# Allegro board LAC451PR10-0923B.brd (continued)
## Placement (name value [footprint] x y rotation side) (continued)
RA21  100K_0402_5%  [R_0402]  300.58 73.69 180 top
RA24  4.7K_0402_5%  [R_0402]  290.5 62.07 180 top
RA25  4.7K_0402_5%  [R_0402]  291.36 62.07 0 top
RA26  100K_0402_5%  [R_0402]  275.1 53.5 0 top
RA27  200K_0402_5%  [R_0402]  279.83 55.29 180 top
RA28  100K_0402_5%  [R_0402]  275.1 52.61 0 top
RA29  100K_0402_5%  [R_0402]  280.98 53.31 180 top
RA30  22_0402_5%  [R_0402]  286.74 63.97 90 top
RA31  22_0402_5%  [R_0402]  288.43 63.04 180 top
RA32  33_0402_5%  [R_0402]  287.63 63.97 90 top
RA35  0_0402_5%  [R0402_0OHM]  300.5 63.53 0 top
RA36  0_0402_5%  [R0402_0OHM]  292.2 40.37 270 top
RA37  0_0402_5%  [R0402_0OHM]  283.96 57.1 90 top
RA38  100K_0402_5%  [R_0402]  280.07 54.2 0 top
RA39  0_0805_5%  [R0805_0OHM]  279.12 73.86 90 top
RA44  100K_0402_5%  [R_0402]  294.66 62.01 0 top
RA45  0_0402_5%  [R0402_0OHM]  281.99 52.36 180 top
RC1  100K_0402_5%  [R_0402]  167.89 95.61 0 top
RC2  24.9_0402_1%  [R_0402]  144.78 100.78 180 top
RC3  100_0402_1%  [R_0402]  164.82 112.1 90 top
RC4  200_0402_1%  [R_0402]  175.24 85.63 180 top
RC5  121_0402_1%  [R_0402]  162.69 75.11 270 top
RC6  80.6_0402_1%  [R_0402]  163.58 75.11 270 top
RC7  100_0402_1%  [R_0402]  165.95 73.33 270 top
RC10  1K_0402_1%  [R_0402]  185.27 87.58 180 bottom
RC11  1K_0402_1%  [R_0402]  182.31 72.39 90 top
RC12  1K_0402_5%  [R_0402]  177.01 98.6 90 top
RC13  10K_0402_5%  [R_0402]  174.9 68.54 180 top
RC14  1K_0402_5%  [R_0402]  177.9 98.6 90 top
RC15  1K_0402_5%  [R_0402]  178.84 94.95 180 top
RC16  22_0402_5%  [R_0402]  177.7 73.31 270 top
RC17  1K_0402_5%  [R_0402]  178.84 94.06 180 top
RC18  22_0402_5%  [R_0402]  176.81 73.31 270 top
RC19  499_0402_1%  [R_0402]  252.75 88.35 180 top
RC20  499_0402_1%  [R_0402]  252.75 89.37 180 top
RC21  10K_0402_1%  [R_0402]  172.82 74.13 90 top
RC22  22_0402_5%  [R_0402]  180.05 73.31 270 top
RC23  2.2K_0402_5%  [R_0402]  173.48 93.15 0 top
RC24  22_0402_5%  [R_0402]  179.16 73.31 270 top
RC25  10K_0402_5%  [R_0402]  176.96 92.59 270 top
RC26  10K_0402_5%  [R_0402]  171.93 75.04 270 top
RC27  8.2K_0402_5%  [R_0402]  173.71 75.04 270 top
RC28  33_0402_5%  [R_0402]  186.19 90.44 0 bottom
RC29  33_0402_5%  [R_0402]  186.28 100.95 270 bottom
RC30  1K_0402_5%  [R_0402]  196.71 87.71 90 bottom
RC31  1K_0402_5%  [R_0402]  202.14 87.71 90 bottom
RC32  0_0402_5%  [R_0402]  190.76 85.33 0 bottom
RC33  0_0402_5%  [R_0402]  192.52 85.33 0 bottom
RC34  0_0402_5%  [R_0402]  194.27 85.33 0 bottom
RC35  0_0402_5%  [R_0402]  196.54 85.73 0 bottom
RC36  0_0402_5%  [R_0402]  198.52 86.27 270 bottom
RC37  0_0402_5%  [R0402_0OHM]  198.22 98.26 90 bottom
RC38  0_0402_5%  [R_0402]  199.41 85.4 0 bottom
RC39  33_0402_5%  [R_0402]  197.58 95.72 90 bottom
RC40  0_0402_5%  [R_0402]  196.24 77.94 0 bottom
RC41  0_0402_5%  [R_0402]  203.71 86.83 180 bottom
RC42  0_0402_5%  [R_0402]  197.58 92.16 90 bottom
RC43  33_0402_5%  [R_0402]  195.82 87.71 90 bottom
RC44  113_0402_1%  [R_0402]  170.84 91.93 0 top
RC45  100_0402_1%  [R_0402]  171.68 99.91 90 top
RC46  1M_0402_1%  [R_0402]  153.59 110.22 180 bottom
RC47  10K_0402_5%  [R_0402]  191.28 78.65 0 top
RC48  1K_0402_5%  [R_0402]  167.75 73.37 270 top
RC50  10K_0402_5%  [R_0402]  191.28 75.98 0 top
RC51  10K_0402_5%  [R_0402]  191.28 76.87 0 top
RC52  2.7K_0402_1%  [R_0402]  160.7 95.88 0 top
RC54  10M_0402_5%  [R_0402]  180.44 88.54 90 top
RC56  20K_0402_5%  [R_0402]  169.53 73.34 270 top
RC57  20K_0402_5%  [R_0402]  170.41 73.34 270 top
RC59  10K_0402_5%  [R_0402]  180.87 78.39 0 bottom
RC60  0_0402_5%  [R_0402]  192.25 88.63 270 bottom
RC61  0_0402_5%  [R0402_0OHM]  194.92 88.63 270 bottom
RC62  0_0402_5%  [R0402_0OHM]  191.36 88.63 270 bottom
RC64  0_0402_5%  [R0402_0OHM]  194.03 88.63 270 bottom
RC65  100K_0402_5%  [R_0402]  187.03 87.21 180 bottom
RC67  1K_0402_5%  [R_0402]  176.3 68.72 270 top
RC68  10K_0402_5%  [R_0402]  179.89 66.88 270 top
RC69  1M_0402_5%  [R_0402]  181.43 73.3 270 top
RC71  1K_0402_5%  [R_0402]  130.86 108.85 270 bottom
RC72  8.2K_0402_5%  [R_0402]  180.98 71.05 270 top
RC73  10K_0402_5%  [R_0402]  174.6 75.04 270 top
RC74  10K_0402_5%  [R_0402]  190.93 79.79 180 top
RC75  10K_0402_5%  [R_0402]  166.88 72.45 90 top
RC76  43K_0402_1%  [R_0402]  259.56 81.76 90 top
RC77  1K_0402_5%  [R_0402]  122.58 99.6 0 bottom
RC78  60.4_0402_1%  [R_0402]  131.75 108.85 270 bottom
RC79  49.9_0402_1%  [R_0402]  138.02 109.33 270 bottom
RC80  1K_0402_5%  [R_0402]  136.15 109.05 0 bottom
RC81  51_0402_5%  [R_0402]  139.95 110.31 270 bottom
RC82  51_0402_5%  [R_0402]  142.59 109.32 270 bottom
RC83  1K_0402_5%  [R_0402]  129.08 107.93 90 bottom
RC84  499_0402_1%  [R_0402]  129.97 108.85 270 bottom
RC86  51_0402_5%  [R_0402]  140.85 108.8 270 bottom
RC87  1K_0402_5%  [R_0402]  138.97 108.42 90 bottom
RC88  49.9_0402_1%  [R_0402]  171.93 72.37 270 top
RC89  49.9_0402_1%  [R_0402]  172.82 72.37 270 top
RC90  49.9_0402_1%  [R_0402]  135.27 98.69 180 top
RC91  49.9_0402_1%  [R_0402]  135.27 97.8 180 top
RC92  33_0402_5%  [R_0402]  166.27 69.59 90 top
RC93  33_0402_5%  [R_0402]  164.49 69.59 90 top
RC94  33_0402_5%  [R_0402]  161.11 68.17 90 top
RC95  33_0402_5%  [R_0402]  162.88 68.17 90 top
RC96  200_0402_1%  [R_0402]  169.97 92.72 180 top
RC109  1K_0402_5%  [R_0402]  127.4 99.6 0 bottom
RC110  10K_0402_1%  [R_0402]  126.03 100.62 180 bottom
RC112  10K_0402_1%  [R_0402]  127.4 100.62 0 bottom
RC113  10K_0402_1%  [R_0402]  127.28 107.95 0 bottom
RC114  49.9_0402_1%  [R_0402]  139.85 100.09 180 top
RC115  1.5K_0402_5%  [R_0402]  172.12 111.69 90 top
RC119  0_0402_5%  [R_0402]  108.91 69.93 90 top
RC120  100K_0402_5%  [R_0402]  132.64 107.93 90 bottom
RC121  1K_0402_5%  [R_0402]  117.46 128.34 0 bottom
RC122  0_0402_5%  [R_0402]  116.58 128.22 90 bottom
RC123  1K_0402_5%  [R_0402]  112.44 123.48 180 bottom
RC124  1K_0402_5%  [R_0402]  109.24 123.48 0 bottom
RC126  1K_0402_5%  [R_0402]  121.18 126.65 0 top
RC128  0_0402_5%  [R_0402]  128.69 126.93 180 top
RC129  0_0402_5%  [R_0402]  129.58 128.09 90 top
RC130  51_0402_5%  [R_0402]  145.06 121.7 0 bottom
RC131  51_0402_5%  [R_0402]  137.94 121.7 0 bottom
RC132  150_0402_5%  [R_0402]  125.32 130.41 270 top
RC133  1.5K_0402_5%  [R_0402]  130.63 126.93 180 top
RC134  51_0402_5%  [R_0402]  137.94 120.81 0 bottom
RC135  51_0402_5%  [R_0402]  137.92 119.05 0 bottom
RC136  51_0402_5%  [R_0402]  145.97 119.8 180 bottom
RC137  1K_0402_5%  [R_0402]  136.15 119.48 270 top
RC138  51_0402_5%  [R_0402]  111.59 125.99 0 bottom
RC139  51_0402_5%  [R_0402]  131.32 117.75 0 bottom
RC140  100_0402_1%  [R_0402]  156.82 106.42 270 bottom
RC141  100_0402_1%  [R_0402]  155.94 105.51 90 bottom
RC143  0_0603_5%  [R0603_0OHM]  160.35 111.5 180 top
RC152  56_0402_1%  [R_0402]  134.41 108.85 270 bottom
RC153  220_0402_5%  [R_0402]  135.3 107.93 90 bottom
RC157  100_0402_1%  [R_0402]  133.53 108.85 270 bottom
RC161  100_0402_1%  [R_0402]  130.71 98.21 0 top
RC163  100_0402_1%  [R_0402]  132.55 98.21 0 top
RC165  100_0402_1%  [R_0402]  158.44 87.33 0 top
RC166  100_0402_1%  [R_0402]  155.06 105.51 90 bottom
RC167  100_0402_1%  [R_0402]  160.24 87.19 90 top
RC168  100_0402_1%  [R_0402]  154.18 106.42 270 bottom
RC169  0_0603_5%  [R0603_0OHM]  172.44 111.63 270 bottom
RC170  0_0402_5%  [R0402_0OHM]  164.78 114.6 180 top
RC171  0_0402_5%  [R0402_0OHM]  166.9 111.86 270 bottom
RC173  0_0402_5%  [R0402_0OHM]  164.12 111.86 270 bottom
RC175  2.2K_0402_5%  [R_0402]  174.74 94.22 180 top
RC176  2.2K_0402_5%  [R_0402]  173.29 96.88 0 top
RC177  2.2K_0402_5%  [R_0402]  173.29 95.99 0 top
RC178  2.2K_0402_5%  [R_0402]  174.74 95.1 180 top
RC179  100K_0402_5%  [R_0402]  143.75 111.15 270 bottom
RC180  100K_0402_5%  [R_0402]  144.64 111.15 270 bottom
RC181  100K_0402_5%  [R_0402]  148.18 111.15 270 bottom
RC182  100K_0402_5%  [R_0402]  147.3 111.15 270 bottom
RC183  8.2K_0402_5%  [R_0402]  184.66 73.3 270 top
RC184  8.2K_0402_5%  [R_0402]  171.66 86.51 270 top
RC186  4.7K_0402_5%  [R_0402]  183.26 72.39 90 top
RC187  4.7K_0402_5%  [R_0402]  162.01 69.96 180 top
RC189  10K_0402_5%  [R_0402]  191.28 77.76 0 top
RC190  10K_0402_5%  [R_0402]  190.42 78.65 180 top
RC194  0_0805_5%  [R_0805]  192.82 93.47 270 top
RC211  0_0402_5%  [R0402_0OHM]  187.93 73.17 90 top
RC212  0_0402_5%  [R_0402]  189.2 73.17 90 top
RC214  0_0402_5%  [R0402_0OHM]  180.98 65.39 90 top
RC215  0_0402_5%  [R_0402]  175.35 66.96 270 top
RC216  0_0603_1%  [R0603_0OHM]  113.76 125.38 180 top
RC217  0_0402_5%  [R_0402]  124.43 130.41 270 top
RC218  150_0402_5%  [R_0402]  122.67 129.89 90 top
RC219  10K_0402_5%  [R_0402]  123.54 129.5 90 top
RC220  100K_0402_1%  [R_0402]  176.3 66.96 270 top
RC221  0_0402_5%  [R0402_0OHM]  186.18 120.35 270 bottom
RC222  1K_0402_5%  [R_0402]  184.08 127.08 0 bottom
RC223  1K_0402_5%  [R_0402]  161.99 68.17 90 top
RC224  1K_0402_5%  [R_0402]  178.53 109.2 270 bottom
RC225  8.2K_0402_5%  [R_0402]  176.88 114.02 0 bottom
RC227  8.2K_0402_5%  [R_0402]  178.67 114.91 270 bottom
RC228  0_0402_5%  [R0402_0OHM]  145.06 120.81 0 bottom
RC229  0_0402_5%  [R0402_0OHM]  138.83 119.93 180 bottom
RC230  0_0402_5%  [R0402_0OHM]  139.41 117.55 180 bottom
RC231  0_0402_5%  [R0402_0OHM]  153.88 87.56 0 top
RC234  0_0402_5%  [R_0402]  182.76 90.69 180 bottom
RC235  0_0402_5%  [R0402_0OHM]  181.51 92.44 270 bottom
RC237  10K_0402_5%  [R_0402]  175.58 99.31 270 top
RC238  0_0603_5%  [R_0603]  161.07 112.18 270 bottom
RC239  0_0402_5%  [R_0402]  111.53 124.62 0 bottom
RC240  0_0402_5%  [R_0402]  110.12 125.47 180 bottom
RC241  1.5K_0402_5%  [R_0402]  112.44 122.34 180 bottom
RC242  100K_0402_5%  [R_0402]  173.3 97.76 90 top
RC243  10K_0402_5%  [R_0402]  185.39 68.66 90 top
RC244  0_0402_5%  [R0402_0OHM]  193.14 88.63 270 bottom
RC245  10K_0402_5%  [R_0402]  190.42 76.87 180 top
RC267  10K_0402_5%  [R_0402]  178.36 95.92 180 bottom
RC268  10K_0402_5%  [R_0402]  177.44 95.03 0 bottom
RC270  10K_0402_5%  [R_0402]  175.47 74.13 90 top
RC272  10K_0402_5%  [R_0402]  179.55 78.47 180 bottom
RC276  0_0402_5%  [R_0402]  203.71 85.97 270 bottom
RC278  10K_0402_5%  [R_0402]  179.73 98.21 0 bottom
RC279  10K_0402_5%  [R_0402]  190.42 77.76 180 top
RC281  10K_0402_5%  [R_0402]  179.73 95.92 0 bottom
RC282  100K_0402_5%  [R_0402]  173.47 85.63 180 top
RC283  10K_0402_5%  [R_0402]  191.89 87.92 0 top
RC287  100K_0402_5%  [R_0402]  192.2 75.09 180 top
RC288  10K_0402_5%  [R_0402]  179.79 77.3 180 bottom
RC289  0_0402_5%  [R0402_0OHM]  203.71 87.68 90 bottom
RC290  0_0402_5%  [R0402_0OHM]  179.42 108.29 90 bottom
RC291  10K_0402_5%  [R_0402]  177.65 109.2 270 bottom
RC292  10K_0402_5%  [R_0402]  179.17 92.53 180 bottom
RC295  0_0402_5%  [R0402_0OHM]  154.45 110.22 0 bottom
RC296  0_0402_5%  [R0402_0OHM]  181.32 88.55 0 top
RC297  0_0402_5%  [R_0402]  145.54 110.23 90 bottom
RC298  0_0402_5%  [R_0402]  146.42 110.23 90 bottom
RC299  0_0603_5%  [R0603_0OHM]  166.34 117.32 270 bottom
RC300  0_0402_5%  [R0402_0OHM]  169.59 113.24 270 top
RC301  0_0402_5%  [R0402_0OHM]  191.55 94.92 180 top
RC302  0_0402_5%  [R0402_0OHM]  171.04 112.37 270 top
RC303  0_0402_5%  [R0402_0OHM]  166.15 113.48 270 top
RC304  0_0402_5%  [R0402_0OHM]  173.01 91.02 180 top
RC305  0_0402_5%  [R0402_0OHM]  167.79 89.76 180 top
RC306  0_0402_5%  [R0402_0OHM]  177.91 88.9 180 top
RC307  0_0402_5%  [R0402_0OHM]  177.91 90.09 180 top
RC308  0_0402_5%  [R0402_0OHM]  174.25 92.18 180 top
RC309  0_0603_5%  [R0603_0OHM]  176.88 112.75 270 top
RC310  0_0603_5%  [R0603_0OHM]  174.98 112.75 270 top
RC311  10K_0402_5%  [R_0402]  164.95 74.25 90 top
RC312  100K_0402_5%  [R_0402]  170.72 98.34 270 top
RC313  0_0402_5%  [R_0402]  170.65 93.79 180 top
RC316  1K_0402_5%  [R_0402]  201.24 88.63 270 bottom
RC317  150K_0402_5%  [R_0402]  183.28 88.18 270 bottom
RC318  2.2K_0402_5%  [R_0402]  156.93 122.27 0 bottom
RC319  2.2K_0402_5%  [R_0402]  156.93 123.16 0 bottom
RC320  0_0402_5%  [R_0402]  159.1 120.7 270 bottom
RC323  10K_0402_5%  [R_0402]  181.86 70.13 90 top
RC324  2.7K_0402_1%  [R_0402]  160.84 94.41 270 top
RC325  0_0402_5%  [R0402_0OHM]  190.22 86.45 180 bottom
RC326  150K_0402_5%  [R_0402]  179.16 89.61 180 bottom
RC327  0_0402_5%  [R0402_0OHM]  180.92 89.61 180 bottom
RC328  0_0402_5%  [R0402_0OHM]  136.62 110.42 180 bottom
RC330  49.9K_0402_1%  [R_0402]  179.52 91.37 270 bottom
RC331  49.9K_0402_1%  [R_0402]  178.62 91.37 270 bottom
RC337  0_0402_5%  [R0402_0OHM]  173.87 89.04 0 top
RC338  1K_0402_5%  [R_0402]  173.02 90.13 0 top
RC339  0_0402_5%  [R_0402]  181.51 87.83 270 bottom
RC340  0_0402_5%  [R_0402]  182.38 87.83 270 bottom
RC341  10K_0402_5%  [R_0402]  190.52 105.37 270 top
RC342  10K_0402_5%  [R_0402]  190.03 106.64 0 top
RC344  10K_0402_5%  [R_0402]  179.89 67.75 90 top
RC345  100K_0402_5%  [R_0402]  180.62 77.3 0 bottom
RC346  10K_0402_5%  [R_0402]  179.74 114.6 270 top
RC347  499_0402_1%  [R_0402]  254.15 88.35 0 top
RC348  499_0402_1%  [R_0402]  254.15 89.37 0 top
RC349  100_0402_1%  [R_0402]  187.89 77.94 0 bottom
RD2  470_0402_1%  [R_0402]  107.74 41.21 90 top
RD4  1K_0402_5%  [R_0402]  197.23 39.61 180 top
RD18  1K_0402_1%  [R_0402]  126.24 42.16 270 top
RD19  2_0402_1%  [R_0402]  128.8 42.16 270 top
RD20  1K_0402_1%  [R_0402]  127.85 42.16 270 top
RD21  24.9_0402_1%  [R_0402]  130.67 42.16 0 top
RD22  1K_0402_1%  [R_0402]  206.69 42.02 270 top
RD24  1K_0402_1%  [R_0402]  208.82 42.02 0 top
RD25  24.9_0402_1%  [R_0402]  210.64 41.11 0 top
RD29  0_0402_5%  [R0402_0OHM]  107.74 43.9 270 top
RD30  100K_0402_5%  [R_0402]  81.63 40.6 90 top
RD60  0_0603_5%  [R0603_0OHM]  228.95 52.27 270 top
RD61  1K_0402_5%  [R_0402]  116.76 42.41 270 top
RD62  0_0402_5%  [R_0402]  156.52 46.12 180 top
RD63  0_0402_5%  [R_0402]  156.52 47.1 180 top
RD64  0_0402_5%  [R_0402]  133.63 39.47 180 top
RD65  0_0603_5%  [R0603_0OHM]  147.8 49.64 90 top
RD66  0_0402_5%  [R0402_0OHM]  152.85 46.12 0 top
RD67  0_0402_5%  [R0402_0OHM]  152.85 47.1 0 top
RD68  0_0402_5%  [R0402_0OHM]  126.87 39.48 0 top
RD69  0_0402_5%  [R_0402]  230.48 41.77 180 top
RD70  0_0402_5%  [R0402_0OHM]  230.48 40.88 180 top
RD71  0_0402_5%  [R_0402]  213.03 39.53 180 top
RD72  0_0402_5%  [R0402_0OHM]  228.74 41.77 180 top
RD73  0_0402_5%  [R_0402]  228.74 40.88 180 top
RD74  0_0402_5%  [R0402_0OHM]  207.66 39.52 0 top
RD75  2_0402_1%  [R_0402]  207.93 42.02 270 top
RE5  100K_0402_5%  [R_0402]  226.16 75.93 270 top
RE8  100K_0402_5%  [R_0402]  241.26 62.7 180 top
RE9  100K_0402_5%  [R_0402]  230.17 58.5 90 top
RE10  100K_0402_5%  [R_0402]  231.06 58.5 90 top
RE11  100K_0402_5%  [R_0402]  241.6 69.63 180 top
RE12  100K_0402_5%  [R_0402]  224.18 71.41 0 top
RE17  100K_0402_5%  [R_0402]  227.94 75.93 270 top
RE20  100K_0402_5%  [R_0402]  224.18 70.52 0 top
RE21  10K_0402_5%  [R_0402]  225.73 58.5 90 top
RE24  10K_0402_5%  [R_0402]  239.75 74.76 90 top
RE25  100K_0402_5%  [R_0402]  227.51 58.5 90 top
RE26  10_0402_5%  [R_0402]  226.62 58.5 90 top
RE27  33_0402_5%  [R_0402]  229.72 75.01 90 top
RE31  100K_0402_5%  [R_0402]  242.42 79.36 270 top
RE32  0_0402_5%  [R0402_0OHM]  242.94 82.56 270 top
RE33  10K_0402_5%  [R_0402]  244.19 78.44 90 top
RE35  10K_0402_5%  [R_0402]  264.34 73.69 180 top
RE36  100K_0402_5%  [R_0402]  227.05 75.93 270 top
RE38  10K_0402_5%  [R_0402]  224.18 69.63 0 top
RE42  10K_0402_5%  [R_0402]  244.19 75.9 90 top
RE48  10K_0402_5%  [R_0402]  254.73 58.38 90 top
RE51  10K_0402_5%  [R_0402]  253.85 56.76 180 top
RE55  100K_0402_5%  [R_0402]  255.62 58.38 90 top
RE56  10K_0402_5%  [R_0402]  258.04 75.64 270 top
RE57  1K_0402_5%  [R_0402]  257.02 77.81 90 top
RE58  100K_0402_5%  [R_0402]  256.13 77.81 90 top
RE59  0_0402_5%  [R0402_0OHM]  260.58 75.01 90 top
RE60  43_0402_5%  [R_0402]  261.47 75.01 90 top
RE62  100K_0402_5%  [R_0402]  242.34 75.92 0 top
RE63  100K_0402_5%  [R_0402]  258.8 78.72 270 top
RE64  4.7K_0402_5%  [R_0402]  257.91 77.81 90 top
RE65  100_0402_1%  [R_0402]  260.58 77.81 90 top
RE66  10_0402_5%  [R_0402]  257.4 59.29 270 top
RE67  10K_0402_5%  [R_0402]  249.76 57.88 180 top
RE68  100K_0402_5%  [R_0402]  247.99 58.77 270 top
RE69  8.2K_0402_5%  [R_0402]  259.21 58.4 180 top
RE70  2.2K_0402_5%  [R_0402]  262.46 54.9 90 top
RE71  49.9_0402_1%  [R_0402]  274.06 18.17 270 top
RE72  10K_0402_5%  [R_0402]  280.63 10.28 180 top
RE73  10K_0402_5%  [R_0402]  280.63 8.5 180 top
RE74  10K_0402_5%  [R_0402]  280.63 7.62 180 top
RE75  100K_0402_5%  [R_0402]  280.63 9.39 180 top
RE77  1.58K_0402_1%  [R_0402]  250 60.16 270 top
RE78  1K_0402_5%  [R_0402]  255.75 56.09 90 top
RE79  1K_0402_5%  [R_0402]  245.39 67.73 0 top
RE81  10K_0402_5%  [R_0402]  242.01 82.56 270 top
RE82  10K_0402_5%  [R_0402]  241.12 82.56 270 top
RE84  100K_0402_5%  [R_0402]  233.73 59.42 270 top
RE85  100K_0402_5%  [R_0402]  232.84 59.42 270 top
RE86  10K_0402_5%  [R_0402]  265.96 54.77 0 top
RE88  10K_0402_5%  [R_0402]  264.82 69.3 270 top
RE90  0_0402_5%  [R_0402]  264.26 54.66 180 top
RE274  0_0402_5%  [R_0402]  267.82 55.65 90 top
RE275  0_0402_5%  [R0402_0OHM]  264.34 74.58 180 top
RE277  100K_0402_5%  [R_0402]  252.19 57.67 90 top
RE280  0_0402_5%  [R_0402]  251.47 55.8 180 top
RE288  100_0402_5%  [R_0402]  230.53 39.59 180 top
RE290  0_0402_5%  [R0402_0OHM]  247.44 75.85 180 top
RE292  0_0402_5%  [R_0402]  252.11 56.66 180 top
RE298  100K_0402_5%  [R_0402]  234.62 59.42 270 top
RE299  100K_0402_5%  [R_0402]  235.51 59.42 270 top
RE300  240K_0402_5%  [R_0402]  241.26 61.74 0 top
RE301  10K_0402_5%  [R_0402]  256.66 75.01 90 top
RE304  0_0402_5%  [R_0402]  250.8 81.67 0 top
RE305  0_0402_5%  [R0402_0OHM]  239.89 61.73 270 top
RE306  0_0402_5%  [R_0402]  239.89 59.01 90 top
RE308  0_0402_5%  [R_0402]  262.38 68.59 0 top
RE312  0_0402_5%  [R0402_0OHM]  253.48 82.79 270 top
RE313  10K_0402_5%  [R_0402]  254.42 81.56 0 top
RI13  10K_0402_5%  [R_0402]  274.15 101.63 270 top
RI14  22.1K_0402_1%  [R_0402]  277.43 105.11 180 top
RI15  0_0402_5%  [R0402_0OHM]  284.12 99.09 0 bottom
RI16  0_0402_5%  [R0402_0OHM]  284.12 99.98 0 bottom
RI17  0_0402_5%  [R0402_0OHM]  284.12 97.32 0 bottom
RI18  0_0402_5%  [R0402_0OHM]  284.12 98.21 0 bottom
RI19  0_0402_5%  [R0402_0OHM]  65.44 122.77 90 top
RI20  0_0402_5%  [R0402_0OHM]  64.55 122.77 90 top
RI21  0_0402_5%  [R0402_0OHM]  67.22 122.77 90 top
RI22  0_0402_5%  [R0402_0OHM]  66.33 122.77 90 top
RI23  0_0402_5%  [R0402_0OHM]  90.65 122.77 90 top
RI24  0_0402_5%  [R0402_0OHM]  89.76 122.77 90 top
RI25  0_0402_5%  [R0402_0OHM]  92.43 122.77 90 top
RI26  0_0402_5%  [R0402_0OHM]  91.54 122.77 90 top
RI27  0_0402_5%  [R0402_0OHM]  277.63 96.05 0 top
RI28  0_0402_5%  [R0402_0OHM]  277.63 95.16 0 top
RI29  0_0402_5%  [R0402_0OHM]  277.63 97.82 0 top
RI30  0_0402_5%  [R0402_0OHM]  277.63 96.94 0 top
RI31  0_0402_5%  [R0402_0OHM]  285.8 123.06 0 top
RL1  10K_0402_5%  [R_0402]  253.9 91.6 0 top
RL2  10K_0402_5%  [R_0402]  253.9 90.71 0 top
RL3  0_0402_5%  [R0402_0OHM]  269.29 91.86 180 top
RL4  4.7K_0402_5%  [R_0402]  264.45 88.76 270 top
RL5  10K_0402_5%  [R_0402]  267.12 87.84 90 top
RL6  4.7K_0402_5%  [R_0402]  265.34 87.84 90 top
RL7  0_0402_5%  [R0402_0OHM]  268.89 87.84 90 top
RL8  0_0603_5%  [R0603_0OHM]  267.01 90.65 180 top
RL9  10K_0402_5%  [R_0402]  268.01 88.76 270 top
RL11  1M_0402_5%  [R_0402]  265.02 96.73 90 top
RL12  1K_0402_5%  [R_0402]  254.81 92.49 180 top
RL13  3.01K_0402_1%  [R_0402]  263.88 98.51 90 top
RL14  150_0402_5%  [R_0402]  287.75 120.86 90 top
RL15  75_0402_1%  [R_0402]  269.59 123.55 270 top
RL16  75_0402_1%  [R_0402]  270.86 123.55 270 top
RL17  75_0402_1%  [R_0402]  277.21 123.55 270 top
RL18  75_0402_1%  [R_0402]  278.48 123.55 270 top
RL19  150_0402_5%  [R_0402]  283.08 115.52 90 top
RL20  150_0402_5%  [R_0402]  284.81 118 90 top
RL29  1M_0402_5%  [R_0402]  286.87 121.78 270 top
RL30  1M_0402_5%  [R_0402]  280.91 115.48 0 top
RL34  0_0402_5%  [R0402_0OHM]  267.13 95.86 180 top
RL70  10K_0402_5%  [R_0402]  266.24 87.84 90 top
RL71  2.2_0603_5%  [R_0603]  265.28 103.15 90 top
RL72  2.2_0603_5%  [R_0603]  263.88 103.15 90 top
RL73  2.2_0603_5%  [R_0603]  262.48 103.15 90 top
RL74  2.2_0603_5%  [R_0603]  261.08 103.15 90 top
RL75  2.2_0603_5%  [R_0603]  259.69 103.15 90 top
RL76  2.2_0603_5%  [R_0603]  258.29 103.15 90 top
RL77  2.2_0603_5%  [R_0603]  256.89 103.15 90 top
RL78  2.2_0603_5%  [R_0603]  255.5 103.15 90 top
RN25  10K_0402_5%  [R_0402]  24.86 59.8 270 top
RN26  10K_0402_5%  [R_0402]  22.18 57.31 0 top
RN27  10K_0402_5%  [R_0402]  23.78 49.96 90 top
RN28  10K_0402_5%  [R_0402]  22.18 56.42 0 top
RN30  4.99K_0402_1%  [R_0402]  23.1 54.64 180 top
RN31  4.99K_0402_1%  [R_0402]  37.01 54.26 180 top
RN37  10K_0402_5%  [R_0402]  15.83 38.32 0 top
RN38  10K_0402_5%  [R_0402]  23.94 59.56 180 top
RN39  10K_0402_5%  [R_0402]  23.05 58.2 180 top
RN40  10K_0402_5%  [R_0402]  24.67 50.87 270 top
RN41  10K_0402_5%  [R_0402]  23.1 55.53 180 top
RN42  10K_0402_5%  [R_0402]  30.57 56.8 0 top
RN43  10K_0402_5%  [R_0402]  30.57 55.79 0 top
RN44  10K_0402_5%  [R_0402]  31.15 49.96 90 top
RN45  10K_0402_5%  [R_0402]  32.47 56.8 0 top
RN46  10K_0402_5%  [R_0402]  32.47 55.79 0 top
RN47  10K_0402_5%  [R_0402]  32.04 50.87 270 top
RN49  10K_0402_5%  [R_0402]  22.18 53.76 0 top
RN50  10K_0402_5%  [R_0402]  30.57 54.77 0 top
RN51  10K_0402_5%  [R_0402]  30.26 49.96 90 top
RN52  10K_0402_5%  [R_0402]  23.1 52.87 180 top
RN53  10K_0402_5%  [R_0402]  32.47 54.77 0 top
RN54  10K_0402_5%  [R_0402]  29.37 50.87 270 top
RN55  10K_0402_5%  [R_0402]  38.96 59.04 270 top
RN56  10K_0402_5%  [R_0402]  36.09 56.93 0 top
RN57  10K_0402_5%  [R_0402]  37.87 50.96 0 top
RN58  10K_0402_5%  [R_0402]  36.09 56.04 0 top
RN59  10K_0402_5%  [R_0402]  38.07 58.12 90 top
RN60  10K_0402_5%  [R_0402]  37.01 57.82 180 top
RN61  10K_0402_5%  [R_0402]  38.77 50.02 270 top
RN62  10K_0402_5%  [R_0402]  37.01 55.15 180 top
RN63  10K_0402_5%  [R_0402]  44.54 56.42 0 top
RN64  10K_0402_5%  [R_0402]  44.54 55.41 0 top
RN65  10K_0402_5%  [R_0402]  44.54 53.37 0 top
RN66  10K_0402_5%  [R_0402]  46.31 56.42 0 top
RN67  10K_0402_5%  [R_0402]  46.31 55.41 0 top
RN68  10K_0402_5%  [R_0402]  46.31 53.37 0 top
RN69  10K_0402_5%  [R_0402]  36.09 53.37 0 top
RN70  10K_0402_5%  [R_0402]  44.54 54.39 0 top
RN71  10K_0402_5%  [R_0402]  44.42 50.12 90 top
RN72  10K_0402_5%  [R_0402]  37.01 52.49 180 top
RN73  10K_0402_5%  [R_0402]  46.31 54.39 0 top
RN74  10K_0402_5%  [R_0402]  43.53 51.04 270 top
RN77  0_0402_5%  [R0402_0OHM]  25.69 49.96 90 top
RN78  0_0402_5%  [R0402_0OHM]  26.58 49.96 90 top
RN81  0_0402_5%  [R0402_0OHM]  39.72 50.12 90 top
RN82  0_0402_5%  [R0402_0OHM]  40.61 50.12 90 top
RN99  0_0402_5%  [R0402_0OHM]  11.28 39.45 90 bottom
RPC1  33_0804_8P4R_5%  [RP_0804_8P4R]  183.17 96.23 0 bottom
RPC2  33_0804_8P4R_5%  [RP_0804_8P4R]  183.2 93.02 0 bottom
RPC3  10K_8P4R_5%  [RP_0804_8P4R]  175.6 114.39 90 bottom
RPC4  10K_8P4R_5%  [RP_0804_8P4R]  177.86 100.94 0 bottom
RPC5  10K_8P4R_5%  [RP_0804_8P4R]  174.99 108.57 270 bottom
RPE2  4.7K_8P4R_5%  [RP_0804_8P4R]  264.07 64.94 180 top
RPE3  2.2K_0804_8P4R_5%  [RP_0804_8P4R]  246.19 69.08 180 top
RPE5  100K_0804_8P4R_5%  [RP_0804_8P4R]  246.17 73.07 180 top
RPE6  2.2K_0804_8P4R_5%  [RP_0804_8P4R]  262.92 72.54 0 top
RPE7  10K_8P4R_5%  [RP_0804_8P4R]  275.17 16.71 90 top
RPE8  100K_0804_8P4R_5%  [RP_0804_8P4R]  236.08 75.15 90 top
RPE9  100K_0804_8P4R_5%  [RP_0804_8P4R]  224.7 72.82 180 top
RPE10  100K_0804_8P4R_5%  [RP_0804_8P4R]  262.91 63.43 0 top
RPE11  100K_0804_8P4R_5%  [RP_0804_8P4R]  241.08 73.3 0 top
RPV1  2.2K_0804_8P4R_5%  [RP_0804_8P4R]  223.3 122.45 0 top
RPV2  2.2K_0804_8P4R_5%  [RP_0804_8P4R]  211.62 109.34 270 bottom
RR1  10_0402_5%  [R_0402]  272.25 78.39 0 top
RR16  10K_0402_5%  [R_0402]  268.23 85.89 270 top
RR17  0_0402_5%  [R0402_0OHM]  272.25 80.17 0 top
RR18  0_0402_5%  [R0402_0OHM]  272.7 81.47 0 top
RR19  10K_0402_5%  [R_0402]  265.91 83.92 0 top
RR20  6.2K_0402_1%  [R_0402]  264.59 78.01 180 top
RR21  0_0402_5%  [R0402_0OHM]  271.24 76.18 270 top
RR22  0_0402_5%  [R0402_0OHM]  272.13 76.18 270 top
RR23  0_0402_5%  [R0402_0OHM]  272.25 79.28 0 top
RV1  4.7K_0402_5%  [R_0402]  96.87 110.77 145 top
RV2  4.7K_0402_5%  [R_0402]  94.9 109.57 325 top
RV3  100K_0402_5%  [R_0402]  83.03 111.29 270 top
RV4  270K_0402_5%  [R_0402]  87.73 112.48 90 top
RV5  47K_0402_5%  [R_0402]  86.84 114.26 90 top
RV6  10K_0402_5%  [R_0402]  106.28 115.23 325 top
RV8  10K_0402_5%  [R_0402]  251.69 131.28 90 bottom
RV10  470_0402_1%  [R_0402]  232.55 127.5 90 bottom
RV11  470_0402_1%  [R_0402]  233.44 127.5 90 bottom
RV12  470_0402_1%  [R_0402]  234.33 127.5 90 bottom
RV13  470_0402_1%  [R_0402]  235.21 127.5 90 bottom
RV14  470_0402_1%  [R_0402]  230.77 127.5 90 bottom
RV15  470_0402_1%  [R_0402]  231.66 127.5 90 bottom
RV16  470_0402_1%  [R_0402]  236.1 127.5 90 bottom
RV17  470_0402_1%  [R_0402]  236.99 127.5 90 bottom
RV18  2.2K_0402_5%  [R_0402]  239.49 128.1 90 bottom
RV19  10K_0402_5%  [R_0402]  241.4 128.51 270 top
RV20  20K_0402_5%  [R_0402]  247.42 130.08 0 bottom
RV21  2.2K_0402_5%  [R_0402]  238.61 128.1 90 bottom
RV22  1M_0402_5%  [R_0402]  250.67 131.28 90 bottom
RV50  4.99K_0402_1%  [R_0402]  253.08 124.95 270 top
RV51  4.7K_0402_5%  [R_0402]  250.08 113.34 270 top
RV52  4.7K_0402_5%  [R_0402]  253.97 124.95 270 top
RV53  4.7K_0402_5%  [R_0402]  251.31 110.19 90 top
RV54  4.7K_0402_5%  [R_0402]  253.05 114.97 0 top
RV55  4.7K_0402_5%  [R_0402]  246.14 110.21 90 top
RV56  4.7K_0402_5%  [R_0402]  247.09 110.21 90 top
RV57  4.7K_0402_5%  [R_0402]  248.11 110.21 90 top
RV58  4.7K_0402_5%  [R_0402]  249.12 110.21 90 top
RV60  4.7K_0402_5%  [R_0402]  250.08 110.21 90 top
RV61  4.7K_0402_5%  [R_0402]  254.78 114.97 0 top
RV62  4.7K_0402_5%  [R_0402]  246.14 113.34 270 top
RV63  4.7K_0402_5%  [R_0402]  248.11 113.34 270 top
RV64  4.7K_0402_5%  [R_0402]  247.09 113.34 270 top
RV65  4.7K_0402_5%  [R_0402]  249.12 113.34 270 top
RV67  1M_0402_5%  [R_0402]  240.6 120.7 0 top
RV68  1M_0402_5%  [R_0402]  243.91 123.59 270 top
RV69  100K_0402_5%  [R_0402]  247.98 127.06 270 top
RV70  100K_0402_5%  [R_0402]  248.87 127.06 270 top
RV73  1M_0402_5%  [R_0402]  222.91 111.41 0 top
RV74  1M_0402_5%  [R_0402]  210.92 121.5 90 top
RV75  1M_0402_5%  [R_0402]  217.89 123.34 180 top
RV76  150_0402_1%  [R_0402]  226.11 113.45 180 top
RV77  150_0402_1%  [R_0402]  222.91 114.72 0 top
RV78  150_0402_1%  [R_0402]  226.11 114.72 180 top
RV79  100K_0402_5%  [R_0402]  209.84 109.01 270 top
RV80  1M_0402_5%  [R_0402]  221.83 110.21 0 top
RV81  2.2K_0402_5%  [R_0402]  224.52 110.21 180 top
RV82  1M_0402_5%  [R_0402]  218.74 123.34 0 top
RV83  2.2K_0402_5%  [R_0402]  212.49 108.97 270 top
RV84  1M_0402_5%  [R_0402]  211.6 108.97 270 top
RV85  1M_0402_5%  [R_0402]  210.03 121.5 90 top
RV86  10K_0402_5%  [R_0402]  201.9 112.23 90 bottom
RV87  2.2K_0402_5%  [R_0402]  203.3 105.71 0 bottom
RV88  10K_0402_5%  [R_0402]  223.82 112.43 180 top
RV89  3.74K_0402_1%  [R_0402]  222.91 113.45 0 top
RV90  100K_0402_5%  [R_0402]  206.14 121.95 0 bottom
RV91  100K_0402_5%  [R_0402]  206.55 116.34 180 bottom
RV100  4.7K_0402_5%  [R_0402]  251.31 112.48 90 top
RV501  100K_0402_5%  [R_0402]  216.63 125.31 90 bottom
RV502  100K_0402_5%  [R_0402]  215.75 125.31 90 bottom
RV503  5.1M_0402_5%  [R_0402]  212.82 125.31 90 bottom
RV508  1M_0402_5%  [R_0402]  195.6 120.81 0 bottom
RV509  1M_0402_5%  [R_0402]  195.6 115.22 0 bottom
RV516  2.2K_0402_5%  [R_0402]  210.73 109.01 270 top
RV517  2.2K_0402_5%  [R_0402]  214.25 108.33 90 bottom
RV518  2.2K_0402_5%  [R_0402]  213.27 123.3 180 top
RV519  2.2K_0402_5%  [R_0402]  214.36 121.38 180 bottom
RV600  4.99K_0402_1%  [R_0402]  227.43 114.51 90 top
RV601  4.7K_0402_5%  [R_0402]  243 111.67 180 top
RV602  4.7K_0402_5%  [R_0402]  228.32 115.43 270 top
RV603  4.7K_0402_5%  [R_0402]  238.1 115.43 270 top
RV604  100K_0402_5%  [R_0402]  226.08 107.86 0 top
RV605  100K_0402_5%  [R_0402]  226.08 109.64 0 top
RV606  1M_0402_5%  [R_0402]  241.22 105.32 180 top
RV607  1M_0402_5%  [R_0402]  226.08 105.95 0 top
RV608  100K_0402_5%  [R_0402]  226.08 108.75 0 top
RV609  100K_0402_5%  [R_0402]  226.08 110.52 0 top
RV610  4.7K_0402_5%  [R_0402]  243 113.83 180 top
RV611  4.7K_0402_5%  [R_0402]  243 107.73 180 top
RV612  4.7K_0402_5%  [R_0402]  243 108.8 180 top
RV613  4.7K_0402_5%  [R_0402]  243 109.71 180 top
RV614  4.7K_0402_5%  [R_0402]  243 110.78 180 top
RV615  4.7K_0402_5%  [R_0402]  243 112.94 180 top
RV616  4.7K_0402_5%  [R_0402]  242.08 114.72 0 top
RV617  4.7K_0402_5%  [R_0402]  241.22 107.73 180 top
RV618  4.7K_0402_5%  [R_0402]  241.22 108.8 180 top
RV619  4.7K_0402_5%  [R_0402]  241.22 109.71 180 top
RV620  4.7K_0402_5%  [R_0402]  241.22 110.78 180 top
RV621  4.7K_0402_5%  [R_0402]  237.21 114.51 90 top
RV622  10K_0402_5%  [R_0402]  221.97 125.31 90 bottom
RV623  10K_0402_5%  [R_0402]  96.06 101.38 180 bottom
RV647  5.6_0402_5%  [R_0402]  232.39 127.84 90 top
RV648  200_0402_5%  [R_0402]  233.3 129.93 180 top
RV649  5.6_0402_5%  [R_0402]  233.28 127.84 90 top
RV650  5.6_0402_5%  [R_0402]  234.19 127.84 90 top
RV651  200_0402_5%  [R_0402]  235.09 129.93 180 top
RV652  5.6_0402_5%  [R_0402]  235.08 127.85 90 top
RV653  5.6_0402_5%  [R_0402]  230.6 127.84 90 top
RV654  200_0402_5%  [R_0402]  231.47 129.91 180 top
RV655  5.6_0402_5%  [R_0402]  231.49 127.84 90 top
RV656  5.6_0402_5%  [R_0402]  235.99 127.85 90 top
RV657  200_0402_5%  [R_0402]  236.9 129.93 180 top
RV658  5.6_0402_5%  [R_0402]  236.89 127.85 90 top
RV659  27.4K_0402_1%  [R_0402]  223.83 105.2 180 bottom
RV660  88.7K_0402_1%  [R_0402]  221.94 105.2 180 bottom
RV661  100K_0402_5%  [R_0402]  220.19 107.1 180 bottom
RV662  0_0402_5%  [R0402_0OHM]  213.56 105.81 180 bottom
RZ8  2.2K_0402_5%  [R_0402]  289.41 11.41 270 bottom
RZ9  2.2K_0402_5%  [R_0402]  290.29 11.41 270 bottom
RZ10  1M_0402_5%  [R_0402]  296.31 10.75 180 bottom
RZ18  4.7K_0402_5%  [R_0402]  284.99 11.31 180 bottom
RZ19  4.7K_0402_5%  [R_0402]  284.99 12.21 180 bottom
RZ20  4.7K_0402_5%  [R_0402]  286.97 13.12 180 bottom
RZ21  4.7K_0402_5%  [R_0402]  286.97 14.02 180 bottom
RZ22  0_0402_5%  [R0402_0OHM]  281.68 11.27 0 bottom
RZ23  0_0402_5%  [R0402_0OHM]  281.68 12.18 0 bottom
RZ24  10K_0402_5%  [R_0402]  280.9 19.39 180 top
RZ25  150_0402_5%  [R_0402]  285.39 16.67 0 top
RZ26  0_0402_5%  [R_0402]  284.76 13.08 180 bottom
RZ27  150_0402_5%  [R_0402]  279.19 22.77 180 top
RZ28  330_0402_5%  [R_0402]  285.39 17.69 0 top
RZ29  0_0402_5%  [R_0402]  284.76 13.98 180 bottom
RZ32  150_0402_5%  [R_0402]  279.19 21.37 180 top
RZ34  150_0402_5%  [R_0402]  283.36 21.37 0 top
RZ38  100K_0402_5%  [R_0402]  237.72 58.5 90 top
RZ40  100K_0402_5%  [R_0402]  286.73 112.81 0 top
RZ43  0_0402_5%  [R0402_0OHM]  272.25 90.64 0 top
RZ56  0_0402_5%  [R0402_0OHM]  255.75 52.94 270 top
RZ58  33_0402_5%  [R_0402]  212.82 65.24 90 top
RZ59  33_0402_5%  [R_0402]  209.57 69.63 0 top
RZ60  33_0402_5%  [R_0402]  209.62 75.42 270 top
RZ61  0_0402_5%  [R0402_0OHM]  209.57 71.79 0 top
RZ62  10K_0402_5%  [R_0402]  214.98 66.15 270 top
RZ63  33_0402_5%  [R_0402]  210.51 75.42 270 top
RZ64  0_0402_5%  [R0402_0OHM]  195.32 77.11 90 top
RZ65  0_0402_5%  [R_0402]  194.43 77.11 90 top
RZ69  10K_0402_5%  [R_0402]  212.32 74.51 90 top
RZ70  0_0402_5%  [R0402_0OHM]  245.13 42.67 0 bottom
RZ71  0_0402_5%  [R_0402]  245.13 41.78 0 bottom
RZ72  0_0603_5%  [R_0603]  214.46 76.78 0 top
RZ76  0_0402_5%  [R_0402]  271.29 98.59 0 top
RZ77  0_0402_5%  [R_0402]  271.29 99.48 0 top
RZ78  0_0402_5%  [R_0402]  257.3 52.93 270 top
RZ79  0_0402_5%  [R_0402]  258.19 52.93 270 top
RZ80  0_0402_5%  [R_0402]  259.08 52.93 270 top
RZ81  0_0402_5%  [R_0402]  258.89 54.56 0 top
RZ82  0_0402_5%  [R_0402]  171.35 118.53 0 bottom
RZ83  0_0402_5%  [R_0402]  171.35 117.57 0 bottom
RZ84  0_0402_5%  [R_0402]  286.94 10.73 180 bottom
RZ85  0_0402_5%  [R0402_0OHM]  283.58 10.42 0 bottom
RZ86  0_0402_5%  [R0402_0OHM]  291.58 11.55 270 bottom
RZ87  0_0402_5%  [R_0402]  296.76 7.13 0 top
RZ88  0_0402_5%  [R_0402]  219.77 74.02 270 top
RZ89  0_0402_5%  [R0402_0OHM]  220.69 74.02 270 top
RZ90  10K_0402_5%  [R_0402]  216.01 65.26 90 top
RZ110  10K_0402_5%  [R_0402]  217.08 74.1 180 top
RZ111  10K_0402_5%  [R_0402]  221.28 76.39 270 top
RZ112  0_0402_5%  [R0402_0OHM]  216.93 65.26 90 top
RZ113  100_0402_5%  [R_0402]  217.92 74.1 0 top
RZ114  0_0402_5%  [R_0402]  294.55 11.83 270 bottom
RZ115  0_0402_5%  [R_0402]  293.66 11.83 270 bottom
RZ116  10K_0402_5%  [R_0402]  282.62 13.08 180 bottom
RZ117  10K_0402_5%  [R_0402]  282.62 13.99 180 bottom
RZ118  0_0402_5%  [R0402_0OHM]  284.19 16.72 180 top
RZ120  0_0402_5%  [R_0402]  112.1 74.38 0 top
ST2  -  [CLIP_C5P5]  84.1 97.36 180 bottom
SW1  SS3-CMFTQR9_3P  [SW_SS3-CMFTQR9_3P]  190.3 126.5 180 bottom
SW3  SKRBAAE010_4P  [SW_SKRBAAE010_4P]  293 118.75 270 top
T1  PAD~D  [TPC12]  148.54 99.73 0 top
T2  PAD~D  [TPC12]  146.71 99.74 0 top
T3  PAD~D  [TPC12]  140.93 77.58 180 bottom
T4  PAD~D  [TPC12]  139.68 76.96 180 bottom
T5  PAD~D  [TPC12]  143.08 87 0 top
T6  PAD~D  [TPC12]  143.05 85.45 0 top
T9  PAD~D  [TPC12]  121.64 99.6 180 bottom
T10  PAD~D  [TPC12]  143.56 107.18 180 bottom
T11  PAD~D  [TPC12]  142.26 106.21 180 bottom
T12  PAD~D  [TPC12]  129.7 77.81 180 bottom
T13  PAD~D  [TPC12]  128.31 77.81 180 bottom
T14  PAD~D  [TPC12]  166.62 88.59 0 top
T15  PAD~D  [TPC12]  168.35 88.32 0 top
T16  PAD~D  [TPC12]  128.31 79.16 180 bottom
T17  PAD~D  [TPC12]  129.7 79.16 180 bottom
T50  PAD~D  [TPC12]  125.64 39.85 0 top
T51  PAD~D  [TPC12]  127.74 48.99 0 top
T54  PAD~D  [TPC12]  205.34 39.63 0 top
T55  PAD~D  [TPC12]  207.07 49.09 0 top
T88  PAD~D  [TPC12]  255.71 92.49 270 top
T89  PAD~D  [TPC12]  255.69 91.21 270 top
T97  PAD~D  [TPC12]  236.92 69.45 180 bottom
T98  PAD~D  [TPC12]  240.12 63.66 0 top
T99  PAD~D  [TPC12]  240.21 70.48 0 top
T108  PAD~D  [TPC12]  225.3 112.52 90 top
T113  PAD~D  [TPC12]  129.7 80.5 180 bottom
T114  PAD~D  [TPC12]  128.31 80.5 180 bottom
T115  PAD~D  [TPC12]  166.85 85.38 0 top
T120  PAD~D  [TPC12]  166.82 96.31 0 top
T121  PAD~D  [TPC12]  180.92 74.18 0 top
T122  PAD~D  [TPC12]  156.37 97.53 0 top
T123  PAD~D  [TPC12]  155.38 88.71 0 top
T126  PAD~D  [TPC12]  183.8 78.39 180 bottom
T127  PAD~D  [TPC12]  185.27 78.39 180 bottom
T128  PAD~D  [TPC12]  177.34 84.59 180 bottom
T129  PAD~D  [TPC12]  176.29 85.61 180 bottom
T130  PAD~D  [TPC12]  177.68 78.39 180 bottom
T131  PAD~D  [TPC12]  242.87 69.82 0 top
T132  PAD~D  [TPC12]  124.75 74.56 0 top
TL1  MHPC_NS692417  [MHPC_NS692417_24P]  280.98 113.74 180 bottom
UA1  -  [ALC3235-CG_MQFN48_6X6]  286.01 72.24 270 top
UC1  SKL-U_BGA1356  [SKL-U_BGA_1356P-T]  174.07 103.21 0 bottom
UC5  -  [W25Q128FVSIQ_SO8]  196.05 100.03 270 bottom
UC6  -  [W25Q64FVSSIQ_SO8]  195.93 94.12 270 bottom
UC7  TC7SH08FU_SSOP5~D  [TC7SH08FU_SSOP5]  190.14 88.74 270 bottom
UC8  -  [74CBTLV3126BQ_DHVQFN14_2P5X3]  141.76 118.32 90 bottom
UC12  -  [74AHC1G09GW_TSSOP5]  177.25 112.56 0 bottom
UC13  TC7SH08FU_SSOP5~D  [TC7SH08FU_SSOP5]  162.09 121.08 270 bottom
UC14  TC7SH08FU_SSOP5~D  [TC7SH08FU_SSOP5]  88.53 118.26 90 top
UD1  -  [74AUP1G07GW_TSSOP5]  84 42.39 180 top
UE1  ECE5048-LZY_DQFN132_11X11~D  [ECE5048-LZY_DQFN132_11X11]  238.62 63.23 90 top
UE2  -  [MEC5085-LZY_DQFN132_11X11]  248.92 70.79 270 top
UE3  TC7SH08FU_SSOP5~D  [TC7SH08FU_SSOP5]  252.31 82.75 90 top
UE4  -  [74AUP1G07GW_TSSOP5]  248.91 80.72 90 top
UE5  TC7SH08FU_SSOP5~D  [TC7SH08FU_SSOP5]  254.72 54.2 90 top
UI1  -  [SY6288D20AAC_SOT23-5]  75.48 125.95 270 top
UI2  -  [SY6288D20AAC_SOT23-5]  96.82 125.82 270 top
UI3  -  [PI5USB2544ZHEX_TQFN16_3X3]  275.92 102.64 0 top
UL1  WGI219LM-QREF- A0_QFN48_6X6~D  [WGI217LM-QPN9-A2_QFN48_6X6]  263.17 91.69 90 top
UL2  TC7SH08FU_SSOP5~D  [TC7SH08FU_SSOP5]  254.67 95.4 90 top
UL4  -  [PI3L720ZHEX_TQFN42_9X3P5]  257.47 107.02 0 top
UN4  -  [PS8558BTQFN24GTR2-A_TQFN24_4X4]  28.08 57.08 270 top
UN5  -  [PS8558BTQFN24GTR2-A_TQFN24_4X4]  42.12 56.69 270 top
UR2  -  [RTS5242-GR_QFN32_4X4]  266.27 81.95 0 top
UV2  -  [AP2330W-7_SC59-3]  245.39 127.8 90 bottom
UV7  -  [PS8338BQFN60GTR-A0_QFN60_5X9]  250.72 115.75 90 top
UV8  VMM3320BJGR_BGA168  [VMM3320BJGR_BGA_168P-NH]  213.36 112.54 90 top
UV9  W25X10CVSNIG_SO8  [W25X10BVSNIG_SO8]  203.3 112.6 0 bottom
UV11  PI3C3125LEX_TSSOP14~D  [PI3C3125LEX_TSSOP14]  198.24 121.02 90 bottom
UV12  PI3C3125LEX_TSSOP14~D  [PI3C3125LEX_TSSOP14]  198.24 115.43 90 bottom
UV24  -  [G524B1T11U_SOT23-5]  86.9 109.18 180 top
UV26  -  [PS8338BQFN60GTR-A0_QFN60_5X9]  237.58 112.25 180 top
UV27  -  [SY6288D20AAC_SOT23-5]  218.86 126.07 0 bottom
UV28  -  [TPS22961DNYR_WSON8]  224.8 119.94 0 bottom
UV29  EM5106VT_DFN10_3X3  [APL5930QBI-TRG_TDFN10_3X3]  219.71 104.84 270 bottom
UZ2  EM5209VF_SON14_2X3  [TPS22966DPUR_SON14_2X3]  286.87 109.32 90 top
UZ3  EM5209VF_SON14_2X3  [TPS22966DPUR_SON14_2X3]  248.65 46.21 90 top
UZ4  EM5209VF_SON14_2X3  [TPS22966DPUR_SON14_2X3]  86.59 119.6 270 bottom
UZ5  EM5209VF_SON14_2X3  [TPS22966DPUR_SON14_2X3]  275.43 70.07 270 top
UZ6  TC7SH08FU_SSOP5~D  [TC7SH08FU_SSOP5]  265.98 71.04 270 top
UZ8  -  [AOZ1336_DFN8_2X2]  198.04 79.27 0 top
UZ10  TC7SH08FU_SSOP5~D  [TC7SH08FU_SSOP5]  280.07 15.67 270 top
UZ12  NPCT650JA0YX_QFN32_5X5  [NPCT650JAAYX_QFN32_5X5]  218.29 68.51 180 top
UZ19  -  [TPS22961DNYR_WSON8]  158.89 118.48 0 bottom
UZ20  -  [TPS22961DNYR_WSON8]  168.1 118.54 0 bottom
UZ21  -  [TPS22961DNYR_WSON8]  115.78 128.14 270 top
UZ22  -  [AOZ1336_DFN8_2X2]  194.67 79.83 0 top
UZ26  -  [TPS22961DNYR_WSON8]  112.97 71.17 90 top
YC1  24MHZ_12PF_X3G024000DC1H  [Y_X3G024000DC1H_4P]  155.11 112.35 180 bottom
YC2  32.768KHZ_12.5PF_9H03200042  [Y_9H03200042_2P]  179.51 90.99 0 top
YE1  32.768KHZ_12.5PF_Q13FC135000040  [Y_Q13FC135000040_2P]  249.25 78.52 180 top
YL1  25MHZ_18PF_7V25000034  [Y_7V25000034_4P]  266.66 99.43 270 top
YV2  27MHZ_12PF_X1E000021042600  [Y_X1E000021042600_4P]  222.14 106.42 0 top

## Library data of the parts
C33 CC210 CC219-CC221 CC225 CC226 CC271-CC274 CL28 PC5 PC7 PC104-PC110 PC117 PC118 PC120-PC124 PC201 PC202 PC305 PC306 PC308-PC311 PC508 PC511 PC608 PC612 PC656-PC658 PC672 PC673 PC801 PC803-PC807 PC811 PC812 PC814 PC818-PC820 PC822 PC826 PC827 PC835 PC902 PC1501 PC1503 = C_0805
C42 C43 C263 C294-C316 C319 CA1-CA6 CA12 CA13 CA19 CA22-CA24 CA27 CA28 CA33 CA35 CA41 CA54 CC3-CC8 CC21-CC27 CC32 CC33 CC174-CC179 CC181 CC182 CC185 CC186 CC194 CC195 CC199 CC202-CC209 CC211-CC213 CC215-CC218 CC222 CC224 CC248-CC257 CC264-CC266 CC269 CC288 CC297 CC300-CC308 CC310-CC314 CD2-CD4 CD6-CD11 CD24-CD27 CD31 CD35-CD44 CD54 CD57-CD60 CD63 CD70 CD71 CD74 CD75 CD78-CD85 CD102-CD109 CE8-CE10 CE12 CE14 CE15 CE24 CE26-CE30 CE34-CE40 CE44-CE47 CE52 CI4 CI5 CI13 CI16 CI27-CI31 CL1 CL2 CL5 CL6 CL13 CL14 CL18 CN20-CN26 CN30-CN36 CR23-CR27 CR35 CR37 CR42 CR43 CV1-CV6 CV10 CV11 CV13 CV14 CV17 CV18 CV21 CV22 CV28 CV29 CV60-CV62 CV71-CV80 CV85 CV86 CV89 CV92 CV93 CV96-CV99 CV102-CV111 CV113 CV115 CV119 CV120 CV122 CV123 CV145-CV150 CV152 CV153 CV156 CV157 CV374 CV501-CV509 CV603-CV613 CV616 CV619 CZ13 CZ14 CZ16 CZ20-CZ23 CZ30 CZ31 CZ37 CZ38 CZ41 CZ42 CZ45 CZ46 CZ51-CZ53 CZ55 CZ58 CZ59 CZ65-CZ69 CZ77 CZ84 CZ87 CZ90 CZ91 CZ95 CZ113 CZ115 PC3 PC4 PC100 PC101 PC103 PC113 PC115 PC116 PC127 PC128 PC203 PC204 PC210 PC212-PC214 PC301 PC303 PC307 PC401 PC402 PC408-PC411 PC417-PC420 PC503 PC505-PC507 PC509 PC510 PC601 PC602 PC605 PC613 PC614 PC616-PC621 PC624-PC633 PC636 PC637 PC639-PC647 PC649-PC654 PC659-PC661 PC677 PC679 PC680 PC685 PC686 PC688 PC809 PC810 PC815-PC817 PC823 PC824 PC829-PC831 PC833 PC834 PC901 PC903-PC905 PC1500 PC1502 PC1504 = C_0402
C317 C318 CA9 CA10 CA16 CA18 CA25 CA26 CA29 CA31 CA43 CA44 CA46 CA48 CA49 CA51-CA53 CC279 CC280 CC282-CC287 CC294-CC296 CD12-CD19 CD28 CD29 CD45-CD52 CD61 CD62 CD72 CD73 CD76 CD77 CD86-CD101 CE1 CE7 CE21 CE31 CE32 CI6 CI11 CI33 CI34 CL4 CL12 CR9 CR38 CR40 CV7 CV9 CV12 CV27 CV82 CV87 CV90 CV94 CV101 CV617 CV618 CZ19 CZ54 CZ60 CZ61 CZ72 CZ76 PC1 PC2 PC6 PC102 PC111 PC112 PC114 PC119 PC125 PC126 PC205-PC207 PC209 PC211 PC215-PC220 PC302 PC304 PC312 PC313 PC403 PC404 PC406 PC407 PC412 PC413 PC415 PC416 PC422 PC424 PC501 PC502 PC504 PC603 PC604 PC611 PC622 PC655 PC662 PC671 PC678 PC802 PC808 PC813 PC821 PC825 PC828 PC832 PC906-PC908 PC1001-PC1029 PC1057-PC1061 PC1064-PC1082 PC1129-PC1146 PC1170-PC1181 = C_0603
CA7 CA8 CA11 CA17 CA45 CA47 CA50 CC9 CC10 CC28-CC30 CC214 CC223 CC270 CC281 CD30 CD32 CD64 CE2-CE6 CE11 CE13 CE16-CE20 CE22 CE23 CE25 CI3 CI7 CI10 CI12 CI17 CI19 CL3 CL7-CL11 CL15-CL17 CL19-CL21 CL25-CL27 CN19 CN29 CN41 CN42 CR8 CR10 CR13 CR36 CR39 CR41 CV8 CV23 CV26 CV66 CV69 CV70 CV83 CV84 CV88 CV91 CV95 CV100 CV114 CV118 CV121 CV510 CV600-CV602 CV615 CZ1 CZ2 CZ10-CZ12 CZ15 CZ17 CZ18 CZ24 CZ27-CZ29 CZ34 CZ36 CZ39 CZ40 CZ43 CZ44 CZ47 CZ48 CZ50 CZ64 CZ71 CZ73-CZ75 CZ78 CZ82 CZ85 CZ89 CZ92 CZ94 CZ114 PC1030-PC1056 PC1083-PC1099 PC1125 PC1126 PC1147-PC1153 PC1164 = C_0201
CD20 CD53 = C_D3
CI1 CI8 CI14 = C_1206
CI32 = C_B2-NPM
CL22 = C_1808
CMOS1 = SHORTPADS-NPM: User Part Number: PART#
CZ57 = C_B2
D19 DA4 DA5 DE1 DZ1-DZ7 = RB751S40T1G_SOD523-2
D20 = L30ESD24VC3-2_SOT23-3
DA1-DA3 DA6 DA7 = L03ESDL5V0CC3-2_SOT23-3
DI1 DI4 DI6 DI7 = L05ESDL5V0NA-4_SLP2510P8-10-9
DI2 DI3 DI5 DV4 = AZC199-02SPR7G_SOT23-3
DV1-DV3 PD901 PD905 = BAT54CW_SOT323-3
FD1-FD4 = FIDUCIAL_C40M80
H1-H4 = H_3P4
H5 H6 = H_1P1N
H7 H8 = H_3P2
H10 H27 = H_3P5
H11 H13 H14 H18-H22 H24 = H_2P4
H12 H15 H16 = H_2P5
H17 H26 = H_2P8
H23 H25 = H_4P4
H28 = H_2P3
H29 = H_0P7N
H30 = H_0P9N
JAPS1 = ACES_50506-01841-P01_18P-NPM
JDEG1 = ACES_50521-01041-P01_10P
JDIMM1 JDIMM2 = LOTES_ADDR0107-P005A_260P-T
JDOCK1 = JAE_WD2F144WBHR500-DT_144P
JEDP1 = ACES_50398-04041-001_40P
JFAN1 = ACES_50271-0040N-001_4P
JHDMI1 = CONCR_099BKAC19YBLCNF_19P
JHP1 = SINGA_2SJ3095-022111F_6P-T
JIR1 = E-T_4251K-F06N-40L_6P
JKBTP1 = ACES_50506-02041-P01_20P
JLED1 = ACES_50209-00801-001_8P-T
JLOM1 = SANTA_130456-511_13P-T
JLPDE1 = HB_A531015-SCHR21_10P
JMDP1 = ACON_MAR2E-2061800_20P
JNGFF1 = CONCR_213AAAA32FA_67P
JNGFF2 = BELLW_80149-3221_67P
JNGFF3 = BELLW_80159-2242_67P-T-S
JRTC1 = TYCO_2-1775293-2_2P
JSD1 = T-SOL_156-2000302608_19P_NR
JSIM1 = T-SOL_5-991503004000-6_8P-T
JSPI1 = E-T_6705K-Y20N-00L_20P
JSPK1 = ACES_50279-0040N-001_4P
JTAG1 = SHORTPADS: User Part Number: PART#
JUSB1 JUSB2 = ACON_TARAV-9R1U91_9P
JUSB3 = SINGA_2UB4008-900101F_9P
JUSH1 = E-T_6705K-Y26N-00L_26P
JXDP1 = SAMTE_BSH-030-01-L-D-A_60P
LA2 LA3 = MURAT_BLM15BD601SN1D_2P
LA5 = MURAT_BLM15PX600SN1D_2P
LA6-LA11 = MURAT_BLM15PX330SN1D_2P
LC1 LC2 = MURAT_BLM15HG601SN1D_2P
LED3 = LED_LTW-C193DC-C_2P
LI3 LI4 LI7 LV27 LZ1 = PANAS_EXC24CQ900U_4P
LL1 = TAIYO_BRC2012T4R7MD_2P
LV1 = MURAT_BLM15BB221SN1D_2P
LV3 LV6 LV9 LV12 = TAIYO_MCF12102G900-T_4P-NPM
LV22-LV25 = MURAT_BLM15PX181SN1D_2P
PBATT1 = DEREN_40-42251-01001RHF_10P-T
PC606 = C_D
PC1062 PC1063 PC1127 PC1128 = C_D2
PD1 = BAS40-05W_SC70-3
PD2 PD3 = TVNST52302AB0_SOT523-3
PD4 = RB751V-40_SOD323-2
PD6 PD7 = PESD5V0U2BT_SOT23-3
PD801-PD803 PD904 = SDMK0340L-7-F_SOD323-2
PD902 PD903 = PDS5100H-13_POWERDI5-3
PH601-PH605 PR1-PR3 PR5-PR12 PR14 PR15 PR101-PR103 PR107-PR110 PR113 PR115-PR118 PR203 PR206 PR207 PR209 PR301 PR302 PR306-PR308 PR310 PR311 PR403 PR404 PR407 PR408 PR410 PR411 PR413-PR421 PR424-PR426 PR428 PR501 PR505-PR511 PR601 PR604 PR605 PR608 PR610-PR613 PR617 PR618 PR621-PR623 PR626 PR628-PR633 PR635 PR636 PR638-PR654 PR656-PR658 PR662 PR678 PR680 PR801 PR803 PR805 PR808 PR809 PR812 PR813 PR817 PR818 PR821 PR822 PR825 PR827 PR829-PR832 PR834 PR837 PR902-PR905 PR908-PR912 PR914-PR917 PR920 PR925 PR927 PR929 PR934 PR936 PR1500-PR1503 R6 R41 R252-R268 R271-R273 RA1 RA2 RA5-RA9 RA12-RA14 RA17 RA18 RA21 RA24-RA32 RA38 RA44 RC1-RC7 RC10-RC36 RC38-RC48 RC50-RC52 RC54 RC56 RC57 RC59 RC60 RC65 RC67-RC69 RC71-RC84 RC86-RC96 RC109 RC110 RC112-RC115 RC119-RC124 RC126 RC128-RC141 RC152 RC153 RC157 RC161 RC163 RC165-RC168 RC175-RC184 RC186 RC187 RC189 RC190 RC212 RC215 RC217-RC220 RC222-RC225 RC227 RC234 RC237 RC239-RC243 RC245 RC267 RC268 RC270 RC272 RC276 RC278 RC279 RC281-RC283 RC287 RC288 RC291 RC292 RC297 RC298 RC311-RC313 RC316-RC320 RC323 RC324 RC326 RC330 RC331 RC338-RC342 RC344-RC349 RD2 RD4 RD18-RD22 RD24 RD25 RD30 RD61-RD64 RD69 RD71 RD73 RD75 RE5 RE8-RE12 RE17 RE20 RE21 RE24-RE27 RE31 RE33 RE35 RE36 RE38 RE42 RE48 RE51 RE55-RE58 RE60 RE62-RE75 RE77-RE79 RE81 RE82 RE84-RE86 RE88 RE90 RE274 RE277 RE280 RE288 RE292 RE298-RE301 RE304 RE306 RE308 RE313 RI13 RI14 RL1 RL2 RL4-RL6 RL9 RL11-RL20 RL29 RL30 RL70 RN25-RN28 RN30 RN31 RN37-RN47 RN49-RN74 RR1 RR16 RR19 RR20 RV1-RV6 RV8 RV10-RV22 RV50-RV58 RV60-RV65 RV67-RV70 RV73-RV91 RV100 RV501-RV503 RV508 RV509 RV516-RV519 RV600-RV623 RV647-RV661 RZ8-RZ10 RZ18-RZ21 RZ24-RZ29 RZ32 RZ34 RZ38 RZ40 RZ58-RZ60 RZ62 RZ63 RZ65 RZ69 RZ71 RZ76-RZ84 RZ87 RZ88 RZ90 RZ110 RZ111 RZ113-RZ117 RZ120 = R_0402
PJP1 PJP22 PJP23 PJP35 PJP102 PJP103 PJP201 PJP204 PJP302 PJP601 = JUMP_43X118
PJP6 PJP12 PJP18 PJP21 PJP26 PJP34 PJP36 PJP100 PJP101 PJP202 PJP301 PJP401 PJP402 PJP501 PJP502 PJP602 = JUMP_43X79
PJP9-PJP11 PJP13-PJP16 PJP19 PJP20 PJP25 PJP27 PJP29-PJP32 PJP203 PJP205 PJP403 PJP404 PJP503 PJP504 PJP603 PJP1500 PJP1501 = JUMP_43X39
PJP801 = JUMP_43X118-NPM
PJPDC1 = CVILU_CI0805M1HRC-NH_5P-T
PL1-PL3 = TAIYO_FBMJ4516HS720NT_2P
PL4 = MURAT_BLM15AG102SN1D_2P
PL100 PL101 = CYNTE_PCMC063T-1R5MN_2P
PL201 = PANAS_ETQP3W2R2WFN_2P
PL301 PL601 PL802 = MAG_MMD-05CZ-R68M-X2L_2P
PL402 PL404 PL501 = MAG_MLV-FY12N1R0M-O1L_2P
PL602 = KC_FBMA-L11-4532158_2P-NPM
PL603 PL604 = MAG_MMD06CZER15MG_4P
PL801 = TOKO_FDVE1040-H-3R3M-P3_2P
PQ1 = IMD2AT-108_SC74-6
PQ2 PQ909 = SI2301CDS-T1-GE3_SOT23-3
PQ3 = FDV301N-G_SOT23-3
PQ4 = MMST3904-7-F_SOT323-3
PQ5 PQ905 = FDMC6679AZ_MLP8-5
PQ201 PQ808 = AON6932A_DFN5X6-8-7
PQ501 = AON7934_DFN3X3A8-10
PQ801 PQ803-PQ805 = NTR4502PT1G_SOT23-3
PQ802 PQ903 = SI4835DDY-T1-GE3_SO8
PQ809 PQ906 PQ908 = DMN65D8LW-7_SOT323-3
PQ901 PQ904 = FDS6679AZ-G_SO8
PQ902 PQ907 PQ911 QA2 QA3 QC2 QE2 QL1 QL2 QV3 QZ3 QZ7 = DMN65D8LDW-7_SOT363-6
PQ910 = DMP3099L-7_SOT23-3
PR4 PR104 PR105 PR114 PR119 PR120 PR208 PR210 PR312 PR402 PR406 PR412 PR422 PR423 PR427 PR504 PR602 PR603 PR606 PR607 PR609 PR614 PR616 PR620 PR625 PR659 PR671 PR673 PR679 PR804 PR806 PR807 PR810 PR815 PR816 PR819 PR820 PR828 PR833 PR835 PR836 PR901 PR906 PR907 PR913 PR918 PR919 PR922 PR923 PR926 PR930-PR932 PR937 PR938 RA35-RA37 RA45 RC37 RC61 RC62 RC64 RC170 RC171 RC173 RC211 RC214 RC221 RC228-RC231 RC235 RC244 RC289 RC290 RC295 RC296 RC300-RC308 RC325 RC327 RC328 RC337 RD29 RD66-RD68 RD70 RD72 RD74 RE32 RE59 RE275 RE290 RE305 RE312 RI15-RI31 RL3 RL7 RL34 RN77 RN78 RN81 RN82 RN99 RR17 RR18 RR21-RR23 RV662 RZ22 RZ23 RZ43 RZ56 RZ61 RZ64 RZ70 RZ85 RZ86 RZ89 RZ112 RZ118 = R0402_0OHM
PR13 PR921 RC194 = R_0805
PR100 PR111 PR304 R274 RA3 RA4 RC143 RC169 RC216 RC299 RC309 RC310 RD60 RD65 RL8 = R0603_0OHM
PR106 PR112 PR204 PR303 PR627 PR663 PR676 PR811 PR824 = R_1206
PR201 PR202 PR205 PR405 PR409 PR502 PR619 PR624 PR660 PR661 PR672 PR674 PR814 PR826 PR924 PR928 PR933 PR935 PR939 RC238 RL71-RL78 RZ72 = R_0603
PR802 PR823 = R_1206_4P-D
PRP1 RPC1-RPC5 RPE2 RPE3 RPE5-RPE11 RPV1 RPV2 = RP_0804_8P4R
PU1 = TS5A63157DCKR_SC70-6
PU100 = SY8286BRAC_QFN20_3X3
PU101 PU902 PU903 UC7 UC13 UC14 UE3 UE5 UL2 UZ6 UZ10 = TC7SH08FU_SSOP5
PU102 = SY8286CRAC_QFN20_3X3
PU201 = RT8207PGQW_WQFN20_3X3
PU301 = SYX196DQNC_QFN10_3X3
PU401 = TPS62134CRGT_QFN16_3X3
PU402 = TPS62134BRGT_QFN16_3X3
PU501 = SY8032ABC_SOT23-6
PU502 PU1500 = AP7175SP-13_SO-8EP-8
PU602 = ISL62883CHRTZ-T_TQFN40_5X5
PU603 PU605 = CSD97374CQ4M_SON8_3P5X4P5
PU606 = ISL95808HRZ-TS2378_DFN8_2X2
PU801 = BQ24715URUYR_WQFN28_4X4
PU901 = CD3301RHHR_QFN36_6X6
QA1 QC3 QE11 QR1 QV2 QV4 QV5 QV7 QV9 QV10 = L2N7002WT1G_SC-70-3
QE3-QE7 = MMBT3904WT1G_SC70-3
QV1 = AO6405_TSOP6
QV8 QZ1 QZ9 = LP2301ALT1G_SOT23-3
QZ4 = DDTA114EUA-7-F_SOT323-3
RA39 = R0805_0OHM
ST2 = CLIP_C5P5
SW1 = SW_SS3-CMFTQR9_3P
SW3 = SW_SKRBAAE010_4P
T1-T6 T9-T17 T50 T51 T54 T55 T88 T89 T97-T99 T108 T113-T115 T120-T123 T126-T132 = TPC12
TL1 = MHPC_NS692417_24P
UA1 = ALC3235-CG_MQFN48_6X6
UC1 = SKL-U_BGA_1356P-T
UC5 = W25Q128FVSIQ_SO8
UC6 = W25Q64FVSSIQ_SO8
UC8 = 74CBTLV3126BQ_DHVQFN14_2P5X3
UC12 = 74AHC1G09GW_TSSOP5
UD1 UE4 = 74AUP1G07GW_TSSOP5
UE1 = ECE5048-LZY_DQFN132_11X11
UE2 = MEC5085-LZY_DQFN132_11X11
UI1 UI2 UV27 = SY6288D20AAC_SOT23-5
UI3 = PI5USB2544ZHEX_TQFN16_3X3
UL1 = WGI217LM-QPN9-A2_QFN48_6X6
UL4 = PI3L720ZHEX_TQFN42_9X3P5
UN4 UN5 = PS8558BTQFN24GTR2-A_TQFN24_4X4
UR2 = RTS5242-GR_QFN32_4X4
UV2 = AP2330W-7_SC59-3
UV7 UV26 = PS8338BQFN60GTR-A0_QFN60_5X9
UV8 = VMM3320BJGR_BGA_168P-NH
UV9 = W25X10BVSNIG_SO8
UV11 UV12 = PI3C3125LEX_TSSOP14
UV24 = G524B1T11U_SOT23-5
UV28 UZ19-UZ21 UZ26 = TPS22961DNYR_WSON8
UV29 = APL5930QBI-TRG_TDFN10_3X3
UZ2-UZ5 = TPS22966DPUR_SON14_2X3
UZ8 UZ22 = AOZ1336_DFN8_2X2
UZ12 = NPCT650JAAYX_QFN32_5X5
YC1 = Y_X3G024000DC1H_4P
YC2 = Y_9H03200042_2P
YE1 = Y_Q13FC135000040_2P
YL1 = Y_7V25000034_4P
YV2 = Y_X1E000021042600_4P

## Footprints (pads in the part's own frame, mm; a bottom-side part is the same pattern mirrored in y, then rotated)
74AHC1G09GW_TSSOP5
  oval 0.381x1.346 smd: 1(0,0) 2(0.65,0) 3(1.3,0) 4(1.3,1.79) 5(0,1.79)
74AUP1G07GW_TSSOP5
  oval 0.381x1.346 smd: 1(0,0) 2(0.65,0) 3(1.3,0) 4(1.3,1.79) 5(0,1.79)
74CBTLV3126BQ_DHVQFN14_2P5X3
  oval 1.041x0.254 smd: 1(0,0) 7(2.95,0) 8(2.95,0.5) 14(0,0.5)
  oval 0.254x1.041 smd: 2(0.475,-0.975) 3(0.975,-0.975) 4(1.475,-0.975) 5(1.975,-0.975) 6(2.475,-0.975) 9(2.475,1.475) 10(1.975,1.475) 11(1.475,1.475) 12(0.975,1.475) 13(0.475,1.475)
  rect 1.499x0.991 smd: 15(1.475,0.25)
ACES_50209-00801-001_8P-T
  oval 0.508x1.6 smd: 1(0,0) 2(0.8,0) 3(1.6,0) 4(2.4,0) 5(3.2,0) 6(4,0) 7(4.8,0) 8(5.6,0)
  rect 1.194x1.702 smd: 9(-1.3,-2.25) 10(6.9,-2.25)
ACES_50271-0040N-001_4P
  oval 0.787x1.6 smd: 1(0,0) 2(-1.25,0) 3(-2.5,0) 4(-3.75,0)
  rect 2.108x2.997 smd: 5(2.55,-2.9) 6(-6.3,-2.9)
ACES_50279-0040N-001_4P
  oval 0.787x1.905 smd: 1(0,0) 2(1.25,0) 3(2.5,0) 4(3.75,0)
  rect 1.295x3.353 smd: 5(6.6,-4.925) 6(-2.85,-4.925)
ACES_50398-04041-001_40P
  oval 0.254x1.295 smd: 1(0,0) 2(0.5,0) 3(1,0) 4(1.5,0) 5(2,0) 6(2.5,0) 7(3,0) 8(3.5,0) 9(4,0) 10(4.5,0) 11(5,0) 12(5.5,0) 13(6,0) 14(6.5,0) 15(7,0) 16(7.5,0) 17(8,0) 18(8.5,0) 19(9,0) 20(9.5,0) 21(10,0) 22(10.5,0) 23(11,0) 24(11.5,0) 25(12,0) 26(12.5,0) 27(13,0) 28(13.5,0) 29(14,0) 30(14.5,0) 31(15,0) 32(15.5,0) 33(16,0) 34(16.5,0) 35(17,0) 36(17.5,0) 37(18,0) 38(18.5,0) 39(19,0) 40(19.5,0)
  rect 1.194x3.2 smd: 41(-2.4,1.95) 45(21.9,1.95)
  rect 2.311x1.295 smd: 42(0.85,3.9) 43(9.75,3.9) 44(18.65,3.9)
